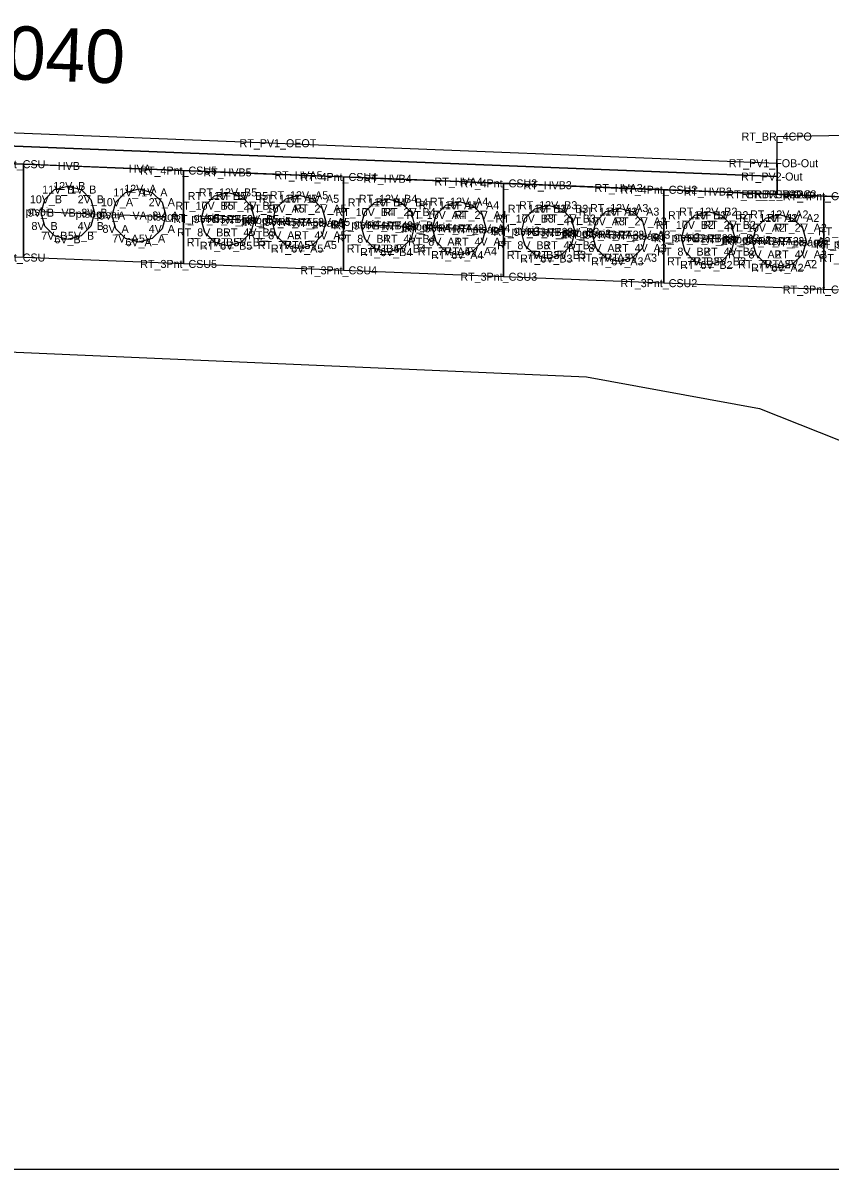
# Model space of a CAD drawing. Extents: x -26 to 1163, y -10 to 9537.
# Drawn here: x 84.24 to 99.37, y 5500 to 5521.48 of the extents above; entities that cross this region are included whole.
import ezdxf

# ---------------------------------------------------------------- set-up
doc = ezdxf.new("R2010")
doc.units = 0
for name, color, linetype in [('Exist Cross Section Cell', 7, 'Continuous'), ('Exist XS Ground Line', 7, 'Continuous'), ('Prop CMT Concrete Structures', 7, 'Continuous'), ('Prop CMT Corridor Surface Symbology Blue', 7, 'Continuous'), ('Prop CMT Pvmt Course 1', 7, 'Continuous'), ('Prop CMT Pvmt Course 2', 7, 'Continuous'), ('Prop XS SE Text', 7, 'Continuous'), ('Scratch_Level_0', 7, 'Continuous')]:
    doc.layers.add(name, color=color, linetype=linetype)

msp = doc.modelspace()

# ---------------------------------------------------------------- linework, layer by layer
at = {"layer": 'Exist Cross Section Cell'}
msp.add_line((80, 5500), (160, 5500), dxfattribs=at)
at = {"layer": 'Exist XS Ground Line'}
msp.add_lwpolyline([(50.408, 5507.818), (57.975, 5511.563), (61.745, 5513.361), (70.287, 5515.157), (70.652, 5515.222), (76.125, 5515.292), (80, 5515.342), (82.665, 5515.377), (85.409, 5515.26), (94.805, 5514.85), (98.043, 5514.258), (104.757, 5511.598), (113.21, 5508.172), (121.817, 5507.493), (125.269, 5507.214), (127.758, 5507.11), (137.804, 5508.533), (143.24, 5508.791), (148.098, 5507.061), (150.039, 5505.923), (155.893, 5501.246), (156.599, 5500.79), (160, 5500.863)], dxfattribs=at)
at = {"layer": 'Prop CMT Concrete Structures'}
for points in [[(98.375, 5518.272), (98.376, 5519.355), (103.875, 5519.465), (103.876, 5519.809), (105.166, 5519.809), (105.167, 5518)], [(81.25, 5518.957), (82.083, 5518.923), (83.417, 5518.87), (84.25, 5518.837)], [(84.25, 5518.837), (84.25, 5517.087)], [(84.25, 5518.837), (85.083, 5518.803), (86.417, 5518.75), (87.25, 5518.717)], [(84.25, 5517.087), (84.25, 5518.837)], [(87.25, 5518.717), (88.083, 5518.683), (89.417, 5518.63), (90.25, 5518.597)], [(87.25, 5516.967), (87.25, 5518.717)], [(87.25, 5518.717), (87.25, 5516.967)], [(84.583, 5517.928), (84.65, 5518.178), (84.833, 5518.361), (85.083, 5518.428)], [(85.083, 5518.428), (85.333, 5518.361), (85.516, 5518.178), (85.583, 5517.928)], [(90.25, 5518.597), (90.25, 5516.847)], [(90.25, 5518.597), (91.083, 5518.563), (92.417, 5518.51), (93.25, 5518.477)], [(90.25, 5516.847), (90.25, 5518.597)], [(93.25, 5518.477), (93.25, 5516.727)], [(93.25, 5518.477), (94.083, 5518.443), (95.417, 5518.39), (96.25, 5518.357)], [(93.25, 5516.727), (93.25, 5518.477)], [(85.917, 5517.875), (85.984, 5518.125), (86.167, 5518.308), (86.417, 5518.375)], [(86.417, 5518.375), (86.667, 5518.308), (86.85, 5518.125), (86.917, 5517.875)], [(87.583, 5517.808), (87.65, 5518.058), (87.833, 5518.241), (88.083, 5518.308)], [(88.083, 5518.308), (88.333, 5518.241), (88.516, 5518.058), (88.583, 5517.808)], [(88.917, 5517.755), (88.984, 5518.005), (89.167, 5518.188), (89.417, 5518.255)], [(89.417, 5518.255), (89.667, 5518.188), (89.85, 5518.005), (89.917, 5517.755)], [(96.25, 5518.357), (96.25, 5516.607)], [(96.25, 5518.357), (97.083, 5518.323), (98.417, 5518.27), (99.25, 5518.237)], [(96.25, 5516.607), (96.25, 5518.357)], [(105.167, 5518), (98.375, 5518.272)], [(99.25, 5518.237), (99.25, 5516.487)], [(99.25, 5518.237), (100.083, 5518.203), (101.417, 5518.15), (102.25, 5518.117)], [(99.25, 5516.487), (99.25, 5518.237)], [(90.583, 5517.688), (90.65, 5517.938), (90.833, 5518.121), (91.083, 5518.188)], [(91.083, 5518.188), (91.333, 5518.121), (91.516, 5517.938), (91.583, 5517.688)], [(91.917, 5517.635), (91.984, 5517.885), (92.167, 5518.068), (92.417, 5518.135)], [(92.417, 5518.135), (92.667, 5518.068), (92.85, 5517.885), (92.917, 5517.635)], [(93.583, 5517.568), (93.65, 5517.818), (93.833, 5518.001), (94.083, 5518.068)], [(94.083, 5518.068), (94.333, 5518.001), (94.516, 5517.818), (94.583, 5517.568)], [(94.917, 5517.515), (94.984, 5517.765), (95.167, 5517.948), (95.417, 5518.015)], [(95.417, 5518.015), (95.667, 5517.948), (95.85, 5517.765), (95.917, 5517.515)], [(85.583, 5517.928), (85.516, 5517.678), (85.333, 5517.495), (85.083, 5517.428), (84.833, 5517.495), (84.65, 5517.678), (84.583, 5517.928)], [(86.917, 5517.875), (86.85, 5517.625), (86.667, 5517.442), (86.417, 5517.375), (86.167, 5517.442), (85.984, 5517.625), (85.917, 5517.875)], [(88.583, 5517.808), (88.516, 5517.558), (88.333, 5517.375), (88.083, 5517.308), (87.833, 5517.375), (87.65, 5517.558), (87.583, 5517.808)], [(96.583, 5517.448), (96.65, 5517.698), (96.833, 5517.881), (97.083, 5517.948)], [(97.083, 5517.948), (97.333, 5517.881), (97.516, 5517.698), (97.583, 5517.448)], [(97.917, 5517.395), (97.984, 5517.645), (98.167, 5517.828), (98.417, 5517.895)], [(98.417, 5517.895), (98.667, 5517.828), (98.85, 5517.645), (98.917, 5517.395)], [(89.917, 5517.755), (89.85, 5517.505), (89.667, 5517.322), (89.417, 5517.255), (89.167, 5517.322), (88.984, 5517.505), (88.917, 5517.755)], [(91.583, 5517.688), (91.516, 5517.438), (91.333, 5517.255), (91.083, 5517.188), (90.833, 5517.255), (90.65, 5517.438), (90.583, 5517.688)], [(92.917, 5517.635), (92.85, 5517.385), (92.667, 5517.202), (92.417, 5517.135), (92.167, 5517.202), (91.984, 5517.385), (91.917, 5517.635)], [(94.583, 5517.568), (94.516, 5517.318), (94.333, 5517.135), (94.083, 5517.068), (93.833, 5517.135), (93.65, 5517.318), (93.583, 5517.568)], [(95.917, 5517.515), (95.85, 5517.265), (95.667, 5517.082), (95.417, 5517.015), (95.167, 5517.082), (94.984, 5517.265), (94.917, 5517.515)], [(97.583, 5517.448), (97.516, 5517.198), (97.333, 5517.015), (97.083, 5516.948), (96.833, 5517.015), (96.65, 5517.198), (96.583, 5517.448)], [(98.917, 5517.395), (98.85, 5517.145), (98.667, 5516.962), (98.417, 5516.895), (98.167, 5516.962), (97.984, 5517.145), (97.917, 5517.395)], [(84.25, 5517.087), (81.25, 5517.207)], [(87.25, 5516.967), (84.25, 5517.087)], [(90.25, 5516.847), (87.25, 5516.967)], [(93.25, 5516.727), (90.25, 5516.847)], [(96.25, 5516.607), (93.25, 5516.727)], [(99.25, 5516.487), (96.25, 5516.607)], [(102.25, 5516.367), (99.25, 5516.487)]]:
    msp.add_lwpolyline(points, dxfattribs=at)
at = {"layer": 'Prop CMT Corridor Surface Symbology Blue'}
for points in [[(84.593, 5517.948), (85.083, 5517.928), (85.573, 5517.909)], [(85.927, 5517.895), (86.417, 5517.875), (86.907, 5517.855)], [(87.593, 5517.828), (88.083, 5517.808), (88.573, 5517.789)], [(88.927, 5517.775), (89.417, 5517.755), (89.907, 5517.735)], [(90.593, 5517.708), (91.083, 5517.688), (91.573, 5517.669)], [(91.927, 5517.655), (92.417, 5517.635), (92.907, 5517.615)], [(93.593, 5517.588), (94.083, 5517.568), (94.573, 5517.549)], [(94.927, 5517.535), (95.417, 5517.515), (95.907, 5517.495)], [(96.593, 5517.468), (97.083, 5517.448), (97.573, 5517.429)], [(97.927, 5517.415), (98.417, 5517.395), (98.907, 5517.375)]]:
    msp.add_lwpolyline(points, dxfattribs=at)
at = {"layer": 'Prop CMT Pvmt Course 1'}
for points in [[(80, 5519.59), (89, 5519.23), (98.376, 5518.855)], [(98.376, 5518.855), (98.376, 5518.605), (80, 5519.34)]]:
    msp.add_lwpolyline(points, dxfattribs=at)
at = {"layer": 'Prop CMT Pvmt Course 2'}
for points in [[(80, 5519.34), (98.376, 5518.605)], [(98.376, 5518.605), (98.375, 5518.272), (80, 5519.007)]]:
    msp.add_lwpolyline(points, dxfattribs=at)

# ---------------------------------------------------------------- texts
at = {"layer": 'Prop XS SE Text'}
msp.add_text('0.040', height=1, rotation=357.7094, dxfattribs=at).set_placement((82.791, 5520.479))
at = {"layer": 'Scratch_Level_0'}
for s, p in [('RT_PV1_OEOT', (88.302, 5519.155)), ('RT_BR_4CPO', (97.71, 5519.28)), ('4Pnt_CSU', (83.714, 5518.762)), ('HVB', (84.897, 5518.728)), ('RT_PV1_FOB-Out', (97.471, 5518.78)), ('HVA', (86.228, 5518.675)), ('RT_4Pnt_CSU5', (86.441, 5518.642)), ('RT_HVB5', (87.624, 5518.608)), ('RT_HVA5', (88.955, 5518.555)), ('RT_4Pnt_CSU4', (89.441, 5518.522)), ('RT_HVB4', (90.624, 5518.488)), ('RT_PV2-Out', (97.701, 5518.53)), ('11V_B', (84.603, 5518.286)), ('12V_B', (84.81, 5518.353)), ('1V_B', (85.128, 5518.286)), ('12V_A', (86.141, 5518.3)), ('RT_HVA4', (91.955, 5518.435)), ('RT_4Pnt_CSU3', (92.441, 5518.402)), ('RT_HVB3', (93.624, 5518.368)), ('RT_HVA3', (94.955, 5518.315)), ('RT_4Pnt_CSU2', (95.441, 5518.282)), ('10V_B', (84.372, 5518.103)), ('2V_B', (85.268, 5518.103)), ('10V_A', (85.703, 5518.05)), ('11V_A', (85.934, 5518.233)), ('1V_A', (86.459, 5518.233)), ('2V_A', (86.599, 5518.05)), ('RT_11V_B5', (87.33, 5518.166)), ('RT_12V_B5', (87.538, 5518.233)), ('RT_1V_B5', (87.855, 5518.166)), ('RT_11V_A5', (88.661, 5518.113)), ('RT_12V_A5', (88.869, 5518.18)), ('RT_1V_A5', (89.186, 5518.113)), ('RT_12V_B4', (90.538, 5518.113)), ('RT_12V_A4', (91.869, 5518.06)), ('RT_HVB2', (96.624, 5518.248)), ('RT_BR_VCB-Out3', (97.427, 5518.197)), ('RT_BR_5CPO', (97.709, 5518.197)), ('RT_HVA2', (97.955, 5518.195)), ('RT_4Pnt_CSU1', (98.483, 5518.162)), ('ptsbi', (84.292, 5517.873)), ('9V_B', (84.335, 5517.853)), ('VB', (84.964, 5517.853)), ('ptsbo', (85.232, 5517.834)), ('3V_B', (85.335, 5517.853)), ('RT_10V_B5', (87.099, 5517.983)), ('RT_2V_B5', (87.995, 5517.983)), ('RT_10V_A5', (88.43, 5517.93)), ('RT_2V_A5', (89.326, 5517.93)), ('RT_10V_B4', (90.099, 5517.863)), ('RT_11V_B4', (90.33, 5518.046)), ('RT_1V_B4', (90.855, 5518.046)), ('RT_2V_B4', (90.995, 5517.863)), ('RT_11V_A4', (91.661, 5517.993)), ('RT_1V_A4', (92.186, 5517.993)), ('RT_11V_B3', (93.33, 5517.926)), ('RT_12V_B3', (93.538, 5517.993)), ('RT_1V_B3', (93.855, 5517.926)), ('RT_11V_A3', (94.661, 5517.873)), ('RT_12V_A3', (94.869, 5517.94)), ('RT_1V_A3', (95.186, 5517.873)), ('RT_12V_B2', (96.538, 5517.873)), ('ptsai', (85.624, 5517.82)), ('9V_A', (85.666, 5517.8)), ('VA', (86.295, 5517.8)), ('ptsao', (86.564, 5517.78)), ('3V_A', (86.666, 5517.8)), ('RT_ptsbi5', (87.019, 5517.753)), ('RT_9V_B5', (87.062, 5517.733)), ('RT_VB5', (87.691, 5517.733)), ('RT_ptsbo5', (87.959, 5517.714)), ('RT_3V_B5', (88.062, 5517.733)), ('RT_ptsai5', (88.351, 5517.7)), ('RT_9V_A5', (88.393, 5517.68)), ('RT_VA5', (89.022, 5517.68)), ('RT_ptsao5', (89.291, 5517.66)), ('RT_3V_A5', (89.393, 5517.68)), ('RT_ptsbi4', (90.019, 5517.633)), ('RT_10V_A4', (91.43, 5517.81)), ('RT_2V_A4', (92.326, 5517.81)), ('RT_10V_B3', (93.099, 5517.743)), ('RT_2V_B3', (93.995, 5517.743)), ('RT_10V_A3', (94.43, 5517.69)), ('RT_2V_A3', (95.326, 5517.69)), ('RT_10V_B2', (96.099, 5517.623)), ('RT_11V_B2', (96.33, 5517.806)), ('RT_1V_B2', (96.855, 5517.806)), ('RT_2V_B2', (96.995, 5517.623)), ('RT_11V_A2', (97.661, 5517.753)), ('RT_12V_A2', (97.869, 5517.82)), ('RT_1V_A2', (98.186, 5517.753)), ('8V_B', (84.402, 5517.603)), ('7V_B', (84.585, 5517.42)), ('5V_B', (85.085, 5517.42)), ('4V_B', (85.268, 5517.603)), ('8V_A', (85.733, 5517.55)), ('4V_A', (86.599, 5517.55)), ('RT_8V_B5', (87.129, 5517.483)), ('RT_4V_B5', (87.995, 5517.483)), ('RT_8V_A5', (88.46, 5517.43)), ('RT_4V_A5', (89.326, 5517.43)), ('RT_9V_B4', (90.062, 5517.613)), ('RT_VB4', (90.691, 5517.613)), ('RT_ptsbo4', (90.959, 5517.594)), ('RT_3V_B4', (91.062, 5517.613)), ('RT_ptsai4', (91.351, 5517.58)), ('RT_9V_A4', (91.393, 5517.56)), ('RT_VA4', (92.022, 5517.56)), ('RT_ptsao4', (92.291, 5517.54)), ('RT_3V_A4', (92.393, 5517.56)), ('RT_ptsbi3', (93.019, 5517.513)), ('RT_9V_B3', (93.062, 5517.493)), ('RT_VB3', (93.691, 5517.493)), ('RT_ptsbo3', (93.959, 5517.474)), ('RT_3V_B3', (94.062, 5517.493)), ('RT_ptsai3', (94.351, 5517.46)), ('RT_9V_A3', (94.393, 5517.44)), ('RT_VA3', (95.022, 5517.44)), ('RT_ptsao3', (95.291, 5517.42)), ('RT_3V_A3', (95.393, 5517.44)), ('RT_10V_A2', (97.43, 5517.57)), ('RT_2V_A2', (98.326, 5517.57)), ('RT_10V_B1', (99.141, 5517.503)), ('6V_B', (84.832, 5517.353)), ('7V_A', (85.916, 5517.367)), ('6V_A', (86.163, 5517.3)), ('5V_A', (86.416, 5517.367)), ('RT_7V_B5', (87.312, 5517.3)), ('RT_6V_B5', (87.559, 5517.233)), ('RT_5V_B5', (87.812, 5517.3)), ('RT_7V_A5', (88.643, 5517.247)), ('RT_5V_A5', (89.143, 5517.247)), ('RT_8V_B4', (90.129, 5517.363)), ('RT_4V_B4', (90.995, 5517.363)), ('RT_8V_A4', (91.46, 5517.31)), ('RT_4V_A4', (92.326, 5517.31)), ('RT_8V_B3', (93.129, 5517.243)), ('RT_4V_B3', (93.995, 5517.243)), ('RT_8V_A3', (94.46, 5517.19)), ('RT_4V_A3', (95.326, 5517.19)), ('RT_ptsbi2', (96.019, 5517.393)), ('RT_9V_B2', (96.062, 5517.373)), ('RT_VB2', (96.691, 5517.373)), ('RT_ptsbo2', (96.959, 5517.354)), ('RT_3V_B2', (97.062, 5517.373)), ('RT_ptsai2', (97.351, 5517.34)), ('RT_9V_A2', (97.393, 5517.32)), ('RT_VA2', (98.022, 5517.32)), ('RT_ptsao2', (98.291, 5517.3)), ('RT_3V_A2', (98.393, 5517.32)), ('RT_ptsbi1', (99.062, 5517.273)), ('RT_9V_B1', (99.105, 5517.253)), ('3Pnt_CSU', (83.714, 5517.012)), ('RT_6V_A5', (88.89, 5517.18)), ('RT_7V_B4', (90.312, 5517.18)), ('RT_6V_B4', (90.559, 5517.113)), ('RT_5V_B4', (90.812, 5517.18)), ('RT_7V_A4', (91.643, 5517.127)), ('RT_6V_A4', (91.89, 5517.06)), ('RT_5V_A4', (92.143, 5517.127)), ('RT_7V_B3', (93.312, 5517.06)), ('RT_6V_B3', (93.559, 5516.993)), ('RT_5V_B3', (93.812, 5517.06)), ('RT_7V_A3', (94.643, 5517.007)), ('RT_5V_A3', (95.143, 5517.007)), ('RT_8V_B2', (96.129, 5517.123)), ('RT_4V_B2', (96.995, 5517.123)), ('RT_8V_A2', (97.46, 5517.07)), ('RT_4V_A2', (98.326, 5517.07)), ('RT_8V_B1', (99.172, 5517.003)), ('RT_3Pnt_CSU5', (86.441, 5516.892)), ('RT_3Pnt_CSU4', (89.441, 5516.772)), ('RT_6V_A3', (94.89, 5516.94)), ('RT_7V_B2', (96.312, 5516.94)), ('RT_6V_B2', (96.559, 5516.873)), ('RT_5V_B2', (96.812, 5516.94)), ('RT_7V_A2', (97.643, 5516.887)), ('RT_6V_A2', (97.89, 5516.82)), ('RT_5V_A2', (98.143, 5516.887)), ('RT_3Pnt_CSU3', (92.441, 5516.652)), ('RT_3Pnt_CSU2', (95.441, 5516.532)), ('RT_3Pnt_CSU1', (98.483, 5516.412))]:
    msp.add_text(s, height=0.15, dxfattribs=at).set_placement(p)

doc.saveas('drawing.dxf')
